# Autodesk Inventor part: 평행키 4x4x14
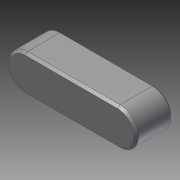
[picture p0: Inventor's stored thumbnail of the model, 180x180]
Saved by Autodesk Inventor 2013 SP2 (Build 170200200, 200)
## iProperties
Created: 2024-07
Part Number: 평행키 4x4x14
Material: Generic
Document SubType Name: Modeling
Designer: 601
Density: 1 g/cm^3
Author: 601
변환 표준: STEP AP214IS
전처리기: Build: 200, Release: 2013 SP2 Update 6 - Date: Thu 07/17/2014
전송 단위: 밀리미터
불확실성: 0.01
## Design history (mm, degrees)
node "평행키 4x4x141"
body "Solid1"
node "기준1"
